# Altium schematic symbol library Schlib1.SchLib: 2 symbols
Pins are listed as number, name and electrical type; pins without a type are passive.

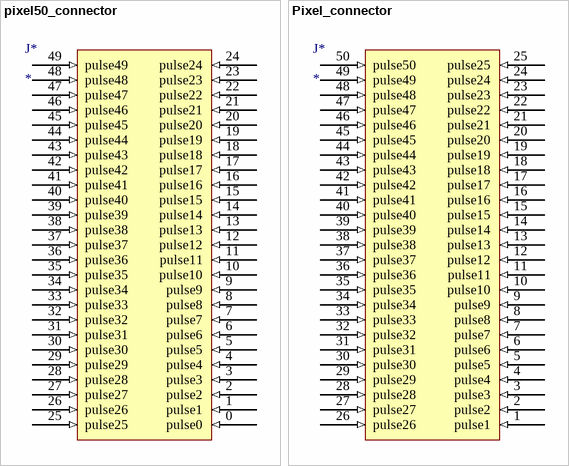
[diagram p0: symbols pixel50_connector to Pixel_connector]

## pixel50_connector
designator J*
footprint pixel50_conn (Pixel Connector 50)
footprint pixel50_conn (Pixel Connector 50)
pins: 0 pulse0 (in), 1 pulse1 (in), 2 pulse2 (in), 3 pulse3 (in), 4 pulse4 (in), 5 pulse5 (in), 6 pulse6 (in), 7 pulse7 (in), 8 pulse8 (in), 9 pulse9 (in), 10 pulse10 (in), 11 pulse11 (in), 12 pulse12 (in), 13 pulse13 (in), 14 pulse14 (in), 15 pulse15 (in), 16 pulse16 (in), 17 pulse17 (in), 18 pulse18 (in), 19 pulse19 (in), 20 pulse20 (in), 21 pulse21 (in), 22 pulse22 (in), 23 pulse23 (in), 24 pulse24 (in), 25 pulse25 (in), 26 pulse26 (in), 27 pulse27 (in), 28 pulse28 (in), 29 pulse29 (in), 30 pulse30 (in), 31 pulse31 (in), 32 pulse32 (in), 33 pulse33 (in), 34 pulse34 (in), 35 pulse35 (in), 36 pulse36 (in), 37 pulse37 (in), 38 pulse38 (in), 39 pulse39 (in), 40 pulse40 (in), 41 pulse41 (in), 42 pulse42 (in), 43 pulse43 (in), 44 pulse44 (in), 45 pulse45 (in), 46 pulse46 (in), 47 pulse47 (in), 48 pulse48 (in), 49 pulse49 (in)

## Pixel_connector
designator J*
footprint Model Name (Model Description)
footprint pixel50_conn (Pixel Connector 50)
pins: 1 pulse1 (in), 2 pulse2 (in), 3 pulse3 (in), 4 pulse4 (in), 5 pulse5 (in), 6 pulse6 (in), 7 pulse7 (in), 8 pulse8 (in), 9 pulse9 (in), 10 pulse10 (in), 11 pulse11 (in), 12 pulse12 (in), 13 pulse13 (in), 14 pulse14 (in), 15 pulse15 (in), 16 pulse16 (in), 17 pulse17 (in), 18 pulse18 (in), 19 pulse19 (in), 20 pulse20 (in), 21 pulse21 (in), 22 pulse22 (in), 23 pulse23 (in), 24 pulse24 (in), 25 pulse25 (in), 26 pulse26 (in), 27 pulse27 (in), 28 pulse28 (in), 29 pulse29 (in), 30 pulse30 (in), 31 pulse31 (in), 32 pulse32 (in), 33 pulse33 (in), 34 pulse34 (in), 35 pulse35 (in), 36 pulse36 (in), 37 pulse37 (in), 38 pulse38 (in), 39 pulse39 (in), 40 pulse40 (in), 41 pulse41 (in), 42 pulse42 (in), 43 pulse43 (in), 44 pulse44 (in), 45 pulse45 (in), 46 pulse46 (in), 47 pulse47 (in), 48 pulse48 (in), 49 pulse49 (in), 50 pulse50 (in)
